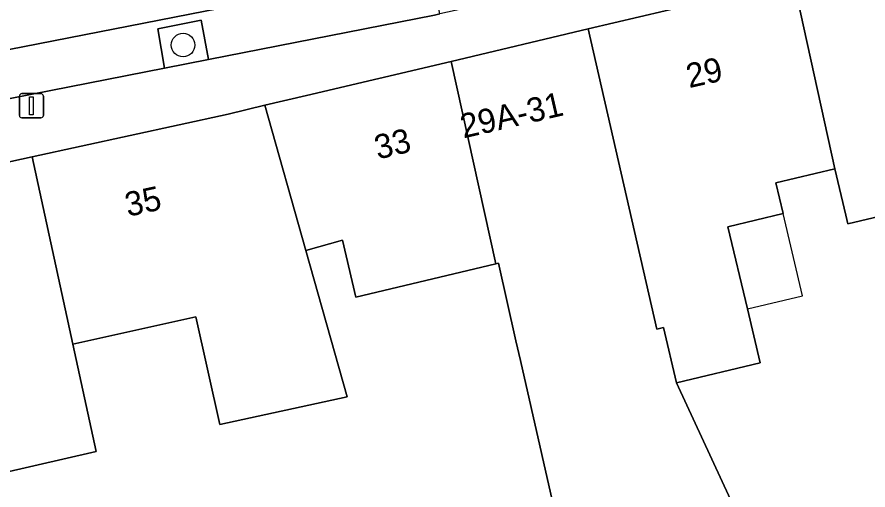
# Model space of a CAD drawing. Extents: x 160377 to 161131, y 383938 to 384853.
# Drawn here: x 160797.69 to 160832.91, y 384501.67 to 384521.23 of the extents above; entities that cross this region are included whole.
import ezdxf

# ---------------------------------------------------------------- set-up
doc = ezdxf.new("R2010")
doc.units = 0
for name, color, linetype in [('IMGEO_Boom', 7, 'Continuous'), ('IMGEO_Erf', 7, 'Continuous'), ('IMGEO_Groenvoorziening', 7, 'Continuous'), ('IMGEO_Lichtmast', 7, 'Continuous'), ('IMGEO_Pand', 7, 'Continuous'), ('IMGEO_Pand_nummerreeks', 7, 'Continuous'), ('IMGEO_Pand_overbouw', 7, 'Continuous'), ('IMGEO_Parkeervlak_open', 7, 'Continuous'), ('IMGEO_Rijbaan_lokaal_open', 7, 'Continuous'), ('IMGEO_Voetpad_open', 7, 'Continuous')]:
    doc.layers.add(name, color=color, linetype=linetype)

msp = doc.modelspace()

# ---------------------------------------------------------------- linework, layer by layer
at = {"layer": 'IMGEO_Boom'}
msp.add_circle((160804.563, 384520.07), 0.489, dxfattribs=at)
at = {"layer": 'IMGEO_Erf'}
for points in [[(160839.119, 384514.345), (160832.071, 384512.67), (160831.983, 384513.038), (160831.529, 384514.948), (160829.089, 384514.368), (160829.39, 384513.101), (160827.108, 384512.558), (160827.915, 384509.164), (160828.448, 384506.924), (160824.985, 384506.101), (160829.021, 384497.374), (160835.248, 384501.579)], [(160820.294, 384499.246), (160818.527, 384507.023), (160818.34, 384507.845), (160817.613, 384511.044), (160817.503, 384511.018), (160811.715, 384509.647), (160811.157, 384512.005), (160809.646, 384511.577), (160811.359, 384505.53), (160806.084, 384504.384), (160805.088, 384508.832), (160800.007, 384507.695), (160800.971, 384503.26), (160794.411, 384501.765)]]:
    msp.add_lwpolyline(points, dxfattribs=at)
at = {"layer": 'IMGEO_Groenvoorziening'}
msp.add_lwpolyline([(160803.793, 384519.115), (160805.621, 384519.473), (160805.314, 384521.101), (160803.515, 384520.742)], close=True, dxfattribs=at)
at = {"layer": 'IMGEO_Lichtmast'}
for p, q in [((160797.792, 384517.16), (160797.792, 384517.96)), ((160797.792, 384517.96), (160797.792, 384517.16)), ((160797.892, 384518.06), (160798.682, 384518.06)), ((160798.682, 384518.06), (160797.892, 384518.06)), ((160798.782, 384517.96), (160798.782, 384517.16)), ((160798.782, 384517.16), (160798.782, 384517.96)), ((160798.682, 384517.06), (160797.892, 384517.06)), ((160797.892, 384517.06), (160798.682, 384517.06))]:
    msp.add_line(p, q, dxfattribs=at)
msp.add_lwpolyline([(160798.212, 384517.935), (160798.362, 384517.935), (160798.362, 384517.185), (160798.212, 384517.185), (160798.212, 384517.935)], dxfattribs=at)
for centre, start, end in [((160797.892, 384517.96), 90, 180), ((160797.892, 384517.96), 90, 180), ((160798.682, 384517.96), 0, 90), ((160798.682, 384517.96), 360, 90), ((160797.892, 384517.16), 180, 270), ((160797.892, 384517.16), 180, 270), ((160798.682, 384517.16), 270, 0), ((160798.682, 384517.16), 270, 0)]:
    msp.add_arc(centre, 0.1, start, end, dxfattribs=at)
at = {"layer": 'IMGEO_Pand'}
for points in [[(160836.849, 384524.407), (160829.818, 384522.743), (160831.529, 384514.948), (160831.983, 384513.038), (160832.071, 384512.67), (160839.119, 384514.345), (160838.644, 384516.451)], [(160831.529, 384514.948), (160829.818, 384522.743), (160821.332, 384520.735), (160824.169, 384508.324), (160824.441, 384508.387), (160824.985, 384506.101), (160828.448, 384506.924), (160827.915, 384509.164), (160827.108, 384512.558), (160829.39, 384513.101), (160829.089, 384514.368)], [(160821.332, 384520.735), (160815.654, 384519.392), (160817.503, 384511.018), (160817.613, 384511.044), (160818.34, 384507.845), (160818.527, 384507.023), (160820.294, 384499.246), (160822.164, 384499.696), (160825.299, 384494.86), (160829.021, 384497.374), (160824.985, 384506.101), (160824.441, 384508.387), (160824.169, 384508.324)], [(160815.654, 384519.392), (160809.674, 384517.977), (160807.944, 384517.586), (160809.646, 384511.577), (160811.157, 384512.005), (160811.715, 384509.647), (160817.503, 384511.018)], [(160807.944, 384517.586), (160806.424, 384517.218), (160798.321, 384515.449), (160800.007, 384507.695), (160805.088, 384508.832), (160806.084, 384504.384), (160811.359, 384505.53), (160809.646, 384511.577)], [(160792.263, 384512.028), (160794.411, 384501.765), (160800.971, 384503.26), (160800.007, 384507.695), (160798.321, 384515.449), (160791.826, 384514.031)]]:
    msp.add_lwpolyline(points, close=True, dxfattribs=at)
at = {"layer": 'IMGEO_Pand_overbouw'}
msp.add_lwpolyline([(160829.39, 384513.101), (160827.108, 384512.558), (160827.915, 384509.164), (160830.196, 384509.706)], close=True, dxfattribs=at)
at = {"layer": 'IMGEO_Parkeervlak_open'}
for points in [[(160803.793, 384519.115), (160803.515, 384520.742), (160805.314, 384521.101), (160805.621, 384519.473), (160814.974, 384521.307), (160815.193, 384521.355), (160814.794, 384523.306), (160769.917, 384514.517)], [(160773.366, 384513.148), (160784.292, 384515.29), (160783.963, 384516.888), (160786.106, 384517.339), (160786.437, 384515.711), (160803.793, 384519.115)]]:
    msp.add_lwpolyline(points, dxfattribs=at)
at = {"layer": 'IMGEO_Rijbaan_lokaal_open'}
msp.add_lwpolyline([(160814.794, 384523.306), (160815.03, 384523.352), (160813.94, 384528.393), (160813.869, 384528.381), (160813.798, 384528.369), (160811.713, 384527.946), (160810.145, 384527.64), (160809.399, 384527.504), (160792.18, 384524.157), (160792.145, 384524.15), (160785.166, 384522.828), (160785.029, 384522.802), (160768.871, 384519.572), (160764.445, 384518.726), (160765.465, 384513.637), (160767.765, 384514.068), (160769.917, 384514.517)], close=True, dxfattribs=at)
at = {"layer": 'IMGEO_Voetpad_open'}
for points in [[(160901.584, 384540.762), (160890.645, 384538.295), (160888.839, 384537.888), (160872.545, 384534.213), (160870.728, 384533.803), (160854.315, 384530.101), (160852.512, 384529.694), (160840.45, 384526.974), (160838.625, 384526.562), (160832.815, 384525.252), (160821.161, 384522.675), (160819.192, 384522.239), (160815.193, 384521.355), (160814.974, 384521.307), (160805.621, 384519.473), (160803.793, 384519.115), (160786.437, 384515.711), (160784.292, 384515.29), (160773.366, 384513.148)], [(160772.659, 384513.262), (160772.776, 384512.843), (160768.147, 384511.974), (160768.624, 384509.5), (160776.123, 384510.948), (160779.019, 384511.567), (160784.031, 384512.547), (160785.415, 384512.818), (160791.826, 384514.031), (160798.321, 384515.449), (160806.424, 384517.218), (160807.944, 384517.586), (160809.674, 384517.977), (160815.654, 384519.392), (160821.332, 384520.735), (160829.818, 384522.743), (160836.849, 384524.407), (160843.878, 384526.07), (160850.787, 384527.704), (160852.74, 384528.157), (160860.097, 384529.748), (160867.05, 384531.251), (160873.862, 384532.724)]]:
    msp.add_lwpolyline(points, dxfattribs=at)

# ---------------------------------------------------------------- texts
at = {"layer": 'IMGEO_Pand_nummerreeks'}
for s, rotation, p in [('29', 12.7197, (160825.508, 384518.286)), ('29A-31', 12.9947, (160816.163, 384516.205)), ('33', 13.3958, (160812.619, 384515.331)), ('35', 12.2728, (160802.279, 384512.964))]:
    msp.add_text(s, height=1, rotation=rotation, dxfattribs=at).set_placement(p)

doc.saveas('drawing.dxf')
